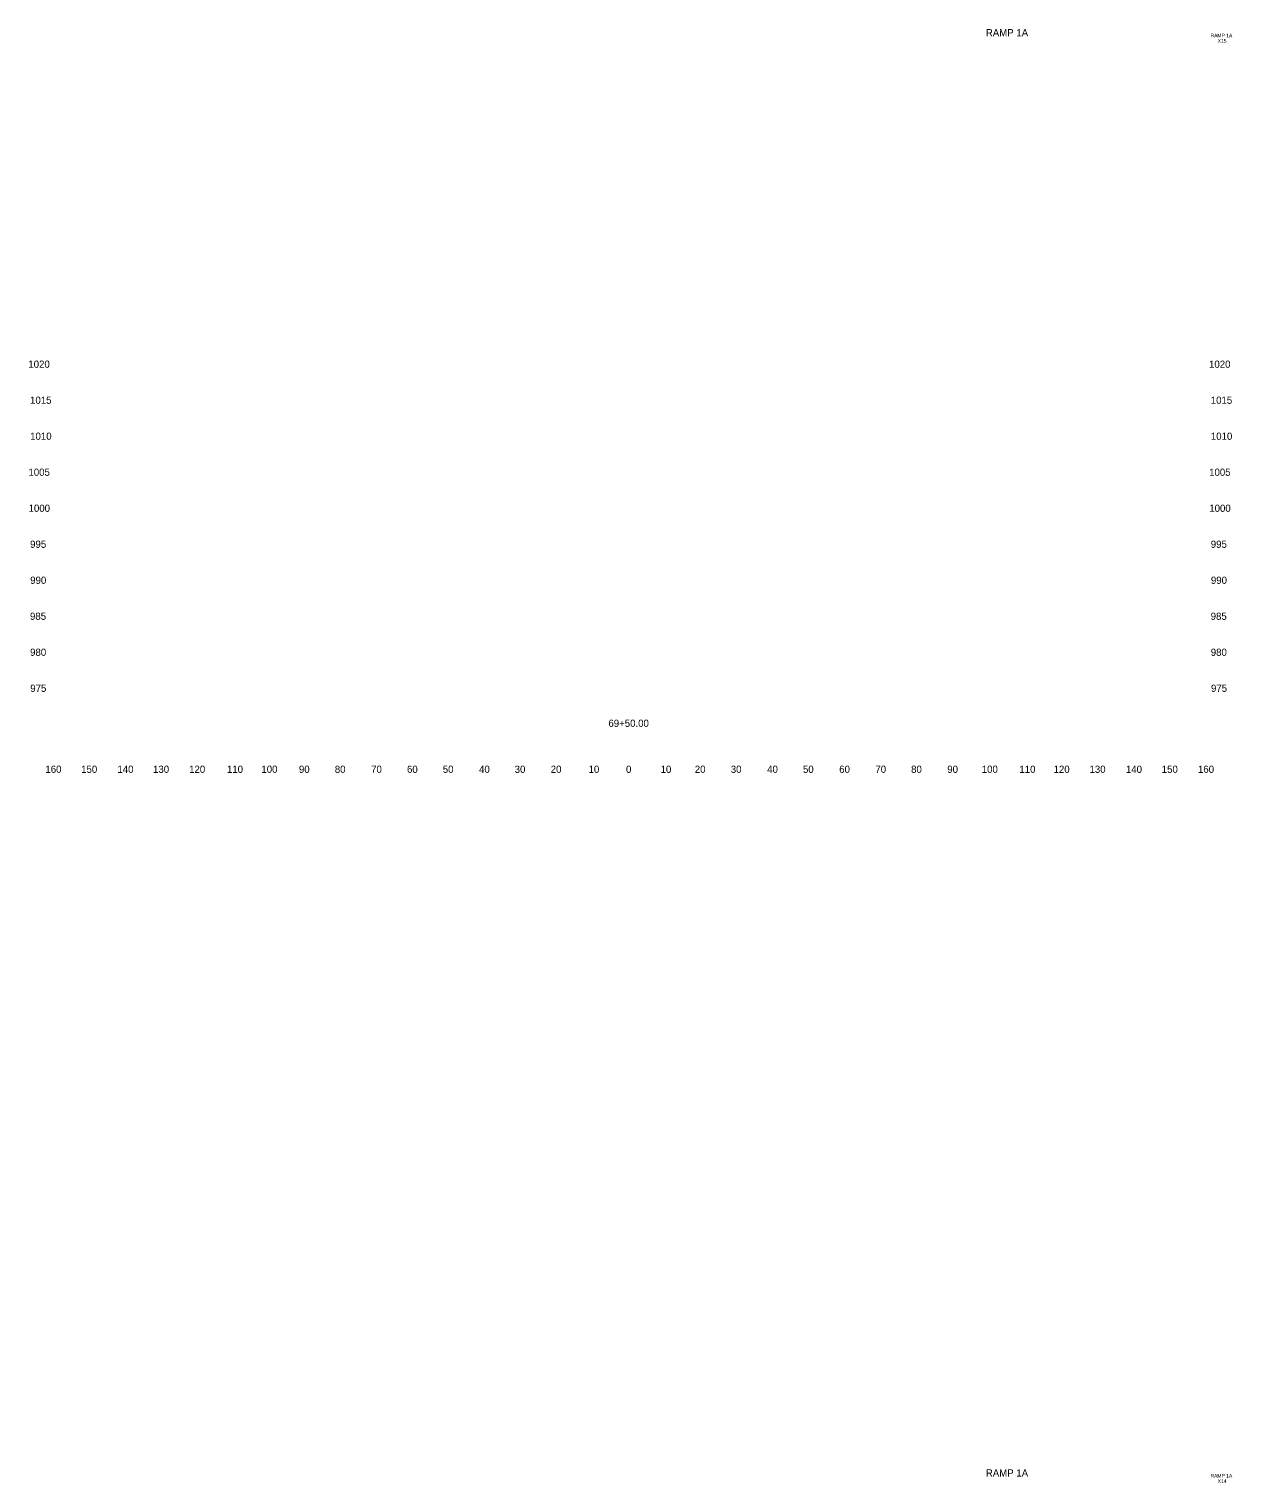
# Model space of a CAD drawing. Extents: x 4994 to 6873, y 4997 to 8804.
# Drawn here: x 5508.6 to 5842.5, y 6400.3 to 6804.1 of the extents above; entities that cross this region are included whole.
import ezdxf

# ---------------------------------------------------------------- set-up
doc = ezdxf.new("R2010")
doc.units = 0
for name, color, linetype in [('RD_SHT_ID', 7, 'Continuous'), ('RD_XS_TX_Offset', 7, 'Continuous'), ('RD_XS_TX_Station', 7, 'Continuous')]:
    doc.layers.add(name, color=color, linetype=linetype)

msp = doc.modelspace()

# ---------------------------------------------------------------- texts
at = {"layer": 'RD_SHT_ID'}
for s, height, p in [('RAMP 1A', 2, (5774.21, 6802.06)), ('RAMP 1A', 1, (5836.57, 6801.8)), ('X15', 1, (5838.57, 6800.3)), ('RAMP 1A', 2, (5774.21, 6402.06)), ('RAMP 1A', 1, (5836.57, 6401.8)), ('X14', 1, (5838.57, 6400.3))]:
    msp.add_text(s, height=height, dxfattribs=at).set_placement(p)
at = {"layer": 'RD_XS_TX_Offset'}
for s, p in [('1020', (5508.37, 6710)), ('1020', (5836.17, 6710)), ('1015', (5508.85, 6700)), ('1015', (5836.65, 6700)), ('1010', (5508.88, 6690)), ('1010', (5836.68, 6690)), ('1005', (5508.4, 6680)), ('1005', (5836.2, 6680)), ('1000', (5508.44, 6670)), ('1000', (5836.24, 6670)), ('995', (5508.86, 6660)), ('995', (5836.66, 6660)), ('990', (5508.89, 6650)), ('990', (5836.69, 6650)), ('985', (5508.83, 6640)), ('985', (5836.63, 6640)), ('980', (5508.86, 6630)), ('980', (5836.66, 6630)), ('975', (5508.91, 6620)), ('975', (5836.71, 6620)), ('160', (5513.1, 6597.5)), ('150', (5523.04, 6597.5)), ('140', (5533.1, 6597.5)), ('130', (5542.99, 6597.5)), ('120', (5553.01, 6597.5)), ('110', (5563.51, 6597.5)), ('100', (5573.07, 6597.5)), ('90', (5583.5, 6597.5)), ('80', (5593.46, 6597.5)), ('70', (5603.54, 6597.5)), ('60', (5613.5, 6597.5)), ('50', (5623.43, 6597.5)), ('40', (5633.5, 6597.5)), ('30', (5643.39, 6597.5)), ('20', (5653.4, 6597.5)), ('10', (5663.91, 6597.5)), ('0', (5674.3, 6597.5)), ('0', (5674.3, 6597.5)), ('10', (5683.91, 6597.5)), ('20', (5693.4, 6597.5)), ('30', (5703.39, 6597.5)), ('40', (5713.5, 6597.5)), ('50', (5723.43, 6597.5)), ('60', (5733.5, 6597.5)), ('70', (5743.54, 6597.5)), ('80', (5753.46, 6597.5)), ('90', (5763.5, 6597.5)), ('100', (5773.07, 6597.5)), ('110', (5783.51, 6597.5)), ('120', (5793.01, 6597.5)), ('130', (5802.99, 6597.5)), ('140', (5813.1, 6597.5)), ('150', (5823.04, 6597.5)), ('160', (5833.1, 6597.5))]:
    msp.add_text(s, height=2, dxfattribs=at).set_placement(p)
at = {"layer": 'RD_XS_TX_Station'}
msp.add_text('69+50.00', height=2, dxfattribs=at).set_placement((5669.42, 6610.27))

doc.saveas('drawing.dxf')
